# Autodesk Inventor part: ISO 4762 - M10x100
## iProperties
Created: 2001-08
Part Number: ISO 4762 - M10x100
Catalog Web Link: file:///D:/Program%20Files/Autodesk/Inventor%205/Content/Iso/index.htm?doNavigateId=932883F9-F3A7-4770-8571-ED868C9DA26C|8C931582D02A477FA87BC5D3591BA4A3|true
Description: Hexagon Socket Head Cap Screw
Document SubType Name: Standard Catalog Part
Standard: ISO 4762 - M10x100
Designer: Martin Budgell
Control State: 0
Master: False
Checked Out: False
Length Units: 11269
Angle Units: 11279
Time Units: 11290
Mass Units: 11283
Shininess: 3
Angle Display Precision: 2
Document Length Units: 11269
Document Angle Units: 11279
Document Time Units: 11290
Document Mass Units: 11283
Document Length Units Precision: 3
Document Angle Units Precision: 2
Compacted: True
CLASSIFICATION: 31161501 un/spsc
MANUFACTURER: ISO Standard System
Density: 0.0
Volumn: 0.0
Area: 0.0
PropertySet Name: Model Information
Author: Martin Budgell
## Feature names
1. Base1
